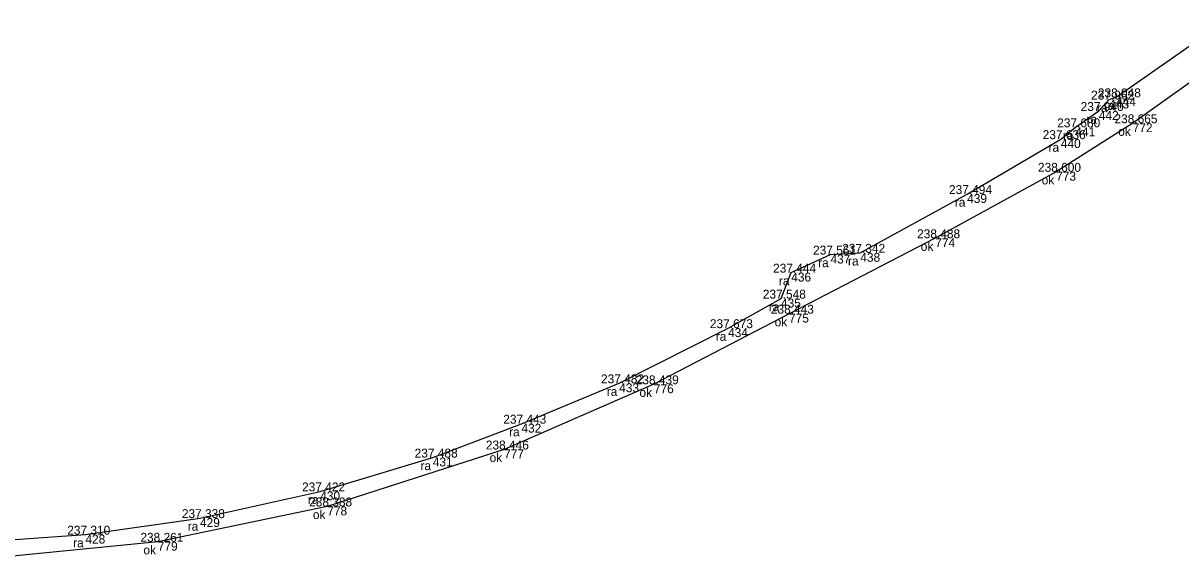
# Model space of a CAD drawing. Extents: x -759609 to -758899, y -1026011 to -1025762.
# Drawn here: x -759447.1 to -759291, y -1026009.1 to -1025936.8 of the extents above; entities that cross this region are included whole.
import ezdxf

# ---------------------------------------------------------------- set-up
doc = ezdxf.new("R2010")
doc.units = 0
for name, color, linetype in [('Vrstva 1', 7, 'Continuous'), ('Vrstva 28', 7, 'Continuous'), ('Vrstva 60', 7, 'Continuous'), ('Vrstva 61', 7, 'Continuous'), ('Vrstva 62', 7, 'Continuous')]:
    doc.layers.add(name, color=color, linetype=linetype)

msp = doc.modelspace()

# ---------------------------------------------------------------- linework, layer by layer
at = {"layer": 'Vrstva 1'}
msp.add_lwpolyline([(-759281.05, -1025938.61), (-759297.45, -1025950.26), (-759307.77, -1025956.8), (-759324.07, -1025965.75), (-759343.79, -1025975.91), (-759362.01, -1025985.42), (-759382.21, -1025994.2), (-759406.05, -1026001.87), (-759428.9, -1026006.63), (-759453.52, -1026009.06), (-759475.49, -1026009.02), (-759498.33, -1026007.13), (-759521.27, -1026003.88), (-759544.21, -1025999.02), (-759569.02, -1025992.07), (-759588.73, -1025985.31), (-759606.94, -1025977.78)], dxfattribs=at)
at = {"layer": 'Vrstva 28'}
msp.add_lwpolyline([(-759454.6, -1026006.75), (-759438.66, -1026005.67), (-759423.21, -1026003.44), (-759407, -1025999.84), (-759391.82, -1025995.29), (-759379.87, -1025990.73), (-759366.69, -1025985.29), (-759352.01, -1025977.86), (-759344.87, -1025973.88), (-759343.49, -1025970.38), (-759338.2, -1025967.95), (-759334.18, -1025967.71), (-759319.77, -1025959.8), (-759307.14, -1025952.4), (-759305.18, -1025950.81), (-759302.02, -1025948.61), (-759300.61, -1025947.07), (-759299.69, -1025946.77), (-759285.37, -1025936.79)], dxfattribs=at)
at = {"layer": 'Vrstva 60'}
for p, q in [((-759300.61, -1025947.07), (-759300.61, -1025947.07)), ((-759299.69, -1025946.77), (-759299.69, -1025946.77)), ((-759302.02, -1025948.61), (-759302.02, -1025948.61)), ((-759305.18, -1025950.81), (-759305.18, -1025950.81)), ((-759297.45, -1025950.26), (-759297.45, -1025950.26)), ((-759307.14, -1025952.4), (-759307.14, -1025952.4)), ((-759307.77, -1025956.8), (-759307.77, -1025956.8)), ((-759319.77, -1025959.8), (-759319.77, -1025959.8)), ((-759324.07, -1025965.75), (-759324.07, -1025965.75)), ((-759338.2, -1025967.95), (-759338.2, -1025967.95)), ((-759334.18, -1025967.71), (-759334.18, -1025967.71)), ((-759343.49, -1025970.38), (-759343.49, -1025970.38)), ((-759344.87, -1025973.88), (-759344.87, -1025973.88)), ((-759343.79, -1025975.91), (-759343.79, -1025975.91)), ((-759352.01, -1025977.86), (-759352.01, -1025977.86)), ((-759366.69, -1025985.29), (-759366.69, -1025985.29)), ((-759362.01, -1025985.42), (-759362.01, -1025985.42)), ((-759379.87, -1025990.73), (-759379.87, -1025990.73)), ((-759391.82, -1025995.29), (-759391.82, -1025995.29)), ((-759382.21, -1025994.2), (-759382.21, -1025994.2)), ((-759407, -1025999.84), (-759407, -1025999.84)), ((-759406.05, -1026001.87), (-759406.05, -1026001.87)), ((-759423.21, -1026003.44), (-759423.21, -1026003.44)), ((-759438.66, -1026005.67), (-759438.66, -1026005.67)), ((-759428.9, -1026006.63), (-759428.9, -1026006.63))]:
    msp.add_line(p, q, dxfattribs=at)

# ---------------------------------------------------------------- texts
for s, p in [('443', (-759300.61, -1025948.27)), ('444', (-759299.69, -1025947.96)), ('442', (-759302.02, -1025949.81)), ('441', (-759305.18, -1025952.01)), ('772', (-759297.45, -1025951.46)), ('440', (-759307.14, -1025953.6)), ('773', (-759307.77, -1025958)), ('439', (-759319.77, -1025961)), ('774', (-759324.07, -1025966.95)), ('437', (-759338.2, -1025969.15)), ('438', (-759334.18, -1025968.92)), ('436', (-759343.49, -1025971.58)), ('435', (-759344.87, -1025975.08)), ('775', (-759343.79, -1025977.11)), ('434', (-759352.01, -1025979.06)), ('433', (-759366.69, -1025986.49)), ('776', (-759362.01, -1025986.62)), ('432', (-759379.87, -1025991.93)), ('431', (-759391.82, -1025996.48)), ('777', (-759382.21, -1025995.4)), ('430', (-759407, -1026001.04)), ('778', (-759406.05, -1026003.07)), ('429', (-759423.21, -1026004.64)), ('428', (-759438.66, -1026006.87)), ('779', (-759428.9, -1026007.83))]:
    msp.add_text(s, height=1.2, dxfattribs=at).set_placement(p)
at = {"layer": 'Vrstva 61'}
for s, p in [('237.962', (-759303.06, -1025947.07)), ('238.048', (-759302.15, -1025946.77)), ('237.940', (-759304.47, -1025948.61)), ('237.680', (-759307.63, -1025950.81)), ('238.665', (-759299.91, -1025950.26)), ('237.636', (-759309.59, -1025952.4)), ('238.600', (-759310.22, -1025956.8)), ('237.494', (-759322.22, -1025959.8)), ('238.488', (-759326.52, -1025965.75)), ('237.561', (-759340.55, -1025967.95)), ('237.342', (-759336.63, -1025967.71)), ('237.444', (-759345.94, -1025970.38)), ('237.548', (-759347.32, -1025973.88)), ('238.443', (-759346.24, -1025975.91)), ('237.673', (-759354.46, -1025977.86)), ('237.482', (-759369.14, -1025985.29)), ('238.439', (-759364.46, -1025985.42)), ('237.443', (-759382.32, -1025990.73)), ('238.446', (-759384.67, -1025994.2)), ('237.488', (-759394.27, -1025995.29)), ('237.422', (-759409.45, -1025999.84)), ('238.388', (-759408.5, -1026001.87)), ('237.338', (-759425.66, -1026003.44)), ('237.310', (-759441.11, -1026005.67)), ('238.261', (-759431.25, -1026006.63))]:
    msp.add_text(s, height=1.2, dxfattribs=at).set_placement(p)
at = {"layer": 'Vrstva 62'}
for s, p in [('ra', (-759302.27, -1025948.77)), ('ra', (-759301.36, -1025948.46)), ('ra', (-759303.69, -1025950.31)), ('ra', (-759306.85, -1025952.51)), ('ok', (-759299.4, -1025951.96)), ('ra', (-759308.8, -1025954.1)), ('ok', (-759309.72, -1025958.5)), ('ra', (-759321.43, -1025961.5)), ('ok', (-759326.02, -1025967.45)), ('ra', (-759339.86, -1025969.65)), ('ra', (-759335.84, -1025969.42)), ('ra', (-759345.15, -1025972.08)), ('ra', (-759346.53, -1025975.58)), ('ok', (-759345.73, -1025977.61)), ('ra', (-759353.67, -1025979.56)), ('ra', (-759368.36, -1025986.99)), ('ok', (-759363.95, -1025987.12)), ('ra', (-759381.53, -1025992.43)), ('ok', (-759384.16, -1025995.9)), ('ra', (-759393.48, -1025996.98)), ('ra', (-759408.66, -1026001.54)), ('ok', (-759407.99, -1026003.57)), ('ra', (-759424.87, -1026005.14)), ('ra', (-759440.32, -1026007.37)), ('ok', (-759430.84, -1026008.33))]:
    msp.add_text(s, height=1.2, dxfattribs=at).set_placement(p)

doc.saveas('drawing.dxf')
